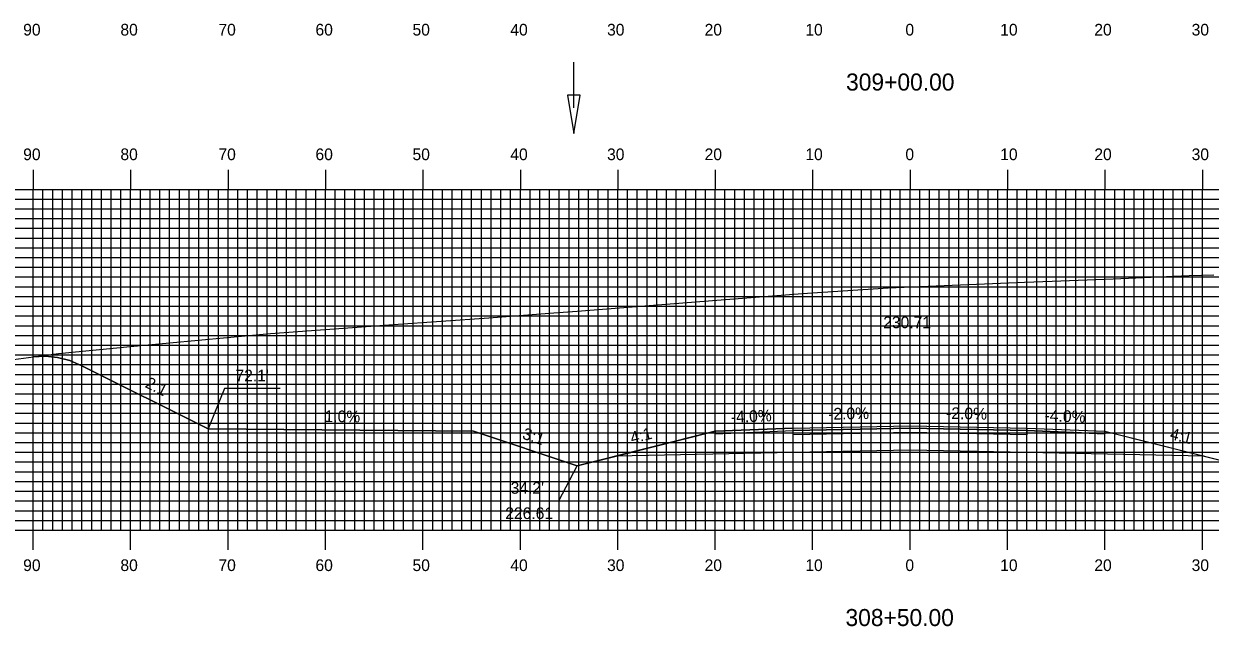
# Model space of a CAD drawing. Extents: x 1817670 to 1818013, y 442591 to 442811.
# Drawn here: x 1817744.6 to 1817866.4, y 442653.8 to 442715.7 of the extents above; entities that cross this region are included whole.
import ezdxf

# ---------------------------------------------------------------- set-up
doc = ezdxf.new("R2010")
doc.units = 0
for name, color, linetype in [('ANNOTATION', 7, 'Continuous'), ('D_Drainage_Ditch_Line', 7, 'Continuous'), ('D_Roadway_Centerline', 7, 'Continuous'), ('D_Roadway_Centerline_Text', 7, 'Continuous'), ('D_Roadway_Edge_Shoulder', 7, 'Continuous'), ('D_Roadway_Edge_TW', 7, 'Continuous'), ('D_Roadway_Pavement', 7, 'Continuous'), ('D_Roadway_SlopeLines', 7, 'Continuous'), ('D_Roadway_SubGrade', 7, 'Continuous'), ('H_V ANNOTATION', 7, 'Continuous'), ('MAJOR', 7, 'Continuous'), ('MINOR', 7, 'Continuous'), ('S_Roadway_Centerline', 7, 'Continuous')]:
    doc.layers.add(name, color=color, linetype=linetype)

msp = doc.modelspace()

# ---------------------------------------------------------------- linework, layer by layer
at = {"layer": 'ANNOTATION'}
for points in [[(1817770.94, 442678.22), (1817765.25, 442678.22), (1817763.55, 442674.09)], [(1817793.87, 442666.68), (1817799.56, 442666.68), (1817801.44, 442670.27)]]:
    msp.add_lwpolyline(points, dxfattribs=at)
at = {"layer": 'D_Drainage_Ditch_Line'}
msp.add_line((1817801.1, 442707.03), (1817801.1, 442711.73), dxfattribs=at)
msp.add_lwpolyline([(1817801.76, 442708.35), (1817800.44, 442708.35), (1817801.1, 442704.41)], close=True, dxfattribs=at)
at = {"layer": 'D_Roadway_Centerline'}
msp.add_lwpolyline([(1817745.61, 442681.47), (1817746.86, 442681.54), (1817748.11, 442681.41), (1817749.36, 442681.08), (1817750.61, 442680.56), (1817763.55, 442674.09), (1817790.81, 442673.82), (1817801.44, 442670.27), (1817805.44, 442671.27), (1817815.61, 442673.82), (1817823.61, 442674.14), (1817835.61, 442674.38), (1817847.61, 442674.14), (1817855.61, 442673.82), (1817865.79, 442671.27), (1817869.79, 442670.27), (1817880.42, 442673.82), (1817887.8, 442673.89), (1817920.61, 442690.3), (1817921.86, 442690.85), (1817923.11, 442691.24), (1817924.36, 442691.47), (1817925.61, 442691.56)], dxfattribs=at)
at = {"layer": 'D_Roadway_Edge_Shoulder'}
for points in [[(1817823.61, 442674.14), (1817815.61, 442673.82), (1817815.61, 442673.57), (1817823.61, 442673.89)], [(1817847.61, 442674.14), (1817855.61, 442673.82), (1817855.61, 442673.57), (1817847.61, 442673.89)]]:
    msp.add_lwpolyline(points, close=True, dxfattribs=at)
at = {"layer": 'D_Roadway_Edge_TW'}
msp.add_lwpolyline([(1817823.61, 442673.89), (1817823.61, 442674.14), (1817835.61, 442674.38), (1817847.61, 442674.14), (1817847.61, 442673.89), (1817835.61, 442674.13)], close=True, dxfattribs=at)
at = {"layer": 'D_Roadway_Pavement'}
msp.add_lwpolyline([(1817823.61, 442673.47), (1817823.61, 442673.89), (1817835.61, 442674.13), (1817847.61, 442673.89), (1817847.61, 442673.47), (1817835.61, 442673.71)], close=True, dxfattribs=at)
at = {"layer": 'D_Roadway_SlopeLines'}
for points in [[(1817790.81, 442673.82), (1817763.55, 442674.09), (1817750.61, 442680.56), (1817749.36, 442681.08), (1817748.11, 442681.41), (1817746.86, 442681.54), (1817745.61, 442681.47)], [(1817801.44, 442670.27), (1817790.81, 442673.82)], [(1817815.61, 442673.82), (1817801.44, 442670.27)], [(1817855.61, 442673.82), (1817869.79, 442670.27)]]:
    msp.add_lwpolyline(points, dxfattribs=at)
at = {"layer": 'D_Roadway_SubGrade'}
msp.add_lwpolyline([(1817823.61, 442671.64), (1817805.44, 442671.27), (1817815.61, 442673.82), (1817815.61, 442673.57), (1817823.61, 442673.89), (1817835.61, 442674.13), (1817847.61, 442673.89), (1817855.61, 442673.57), (1817855.61, 442673.82), (1817865.79, 442671.27), (1817847.61, 442671.64), (1817835.61, 442671.88)], close=True, dxfattribs=at)
at = {"layer": 'MAJOR'}
for p, q in [((1817745.61, 442700.67), (1817745.61, 442698.67)), ((1817755.61, 442700.67), (1817755.61, 442698.67)), ((1817765.61, 442700.67), (1817765.61, 442698.67)), ((1817775.61, 442700.67), (1817775.61, 442698.67)), ((1817785.61, 442700.67), (1817785.61, 442698.67)), ((1817795.61, 442700.67), (1817795.61, 442698.67)), ((1817805.61, 442700.67), (1817805.61, 442698.67)), ((1817815.61, 442700.67), (1817815.61, 442698.67)), ((1817825.61, 442700.67), (1817825.61, 442698.67)), ((1817835.61, 442700.67), (1817835.61, 442698.67)), ((1817845.61, 442700.67), (1817845.61, 442698.67)), ((1817855.61, 442700.67), (1817855.61, 442698.67)), ((1817865.61, 442700.67), (1817865.61, 442698.67)), ((1817695.61, 442698.67), (1817975.61, 442698.67)), ((1817695.61, 442698.67), (1817975.61, 442698.67)), ((1817745.61, 442663.67), (1817745.61, 442698.67)), ((1817755.61, 442663.67), (1817755.61, 442698.67)), ((1817765.61, 442663.67), (1817765.61, 442698.67)), ((1817775.61, 442663.67), (1817775.61, 442698.67)), ((1817785.61, 442663.67), (1817785.61, 442698.67)), ((1817795.61, 442663.67), (1817795.61, 442698.67)), ((1817805.61, 442663.67), (1817805.61, 442698.67)), ((1817815.61, 442663.67), (1817815.61, 442698.67)), ((1817825.61, 442663.67), (1817825.61, 442698.67)), ((1817835.61, 442663.67), (1817835.61, 442698.67)), ((1817845.61, 442663.67), (1817845.61, 442698.67)), ((1817855.61, 442663.67), (1817855.61, 442698.67)), ((1817865.61, 442663.67), (1817865.61, 442698.67)), ((1817695.61, 442693.67), (1817975.61, 442693.67)), ((1817695.61, 442688.67), (1817975.61, 442688.67)), ((1817695.61, 442683.67), (1817975.61, 442683.67)), ((1817695.61, 442678.67), (1817975.61, 442678.67)), ((1817695.61, 442673.67), (1817975.61, 442673.67)), ((1817695.61, 442668.67), (1817975.61, 442668.67)), ((1817695.61, 442663.67), (1817975.61, 442663.67)), ((1817695.61, 442663.67), (1817975.61, 442663.67)), ((1817745.61, 442661.66), (1817745.61, 442663.67)), ((1817755.61, 442661.66), (1817755.61, 442663.67)), ((1817765.61, 442661.66), (1817765.61, 442663.67)), ((1817775.61, 442661.66), (1817775.61, 442663.67)), ((1817785.61, 442661.66), (1817785.61, 442663.67)), ((1817795.61, 442661.66), (1817795.61, 442663.67)), ((1817805.61, 442661.66), (1817805.61, 442663.67)), ((1817815.61, 442661.66), (1817815.61, 442663.67)), ((1817825.61, 442661.66), (1817825.61, 442663.67)), ((1817835.61, 442661.66), (1817835.61, 442663.67)), ((1817845.61, 442661.66), (1817845.61, 442663.67)), ((1817855.61, 442661.66), (1817855.61, 442663.67)), ((1817865.61, 442661.66), (1817865.61, 442663.67))]:
    msp.add_line(p, q, dxfattribs=at)
at = {"layer": 'MINOR'}
for p, q in [((1817746.61, 442663.67), (1817746.61, 442698.67)), ((1817747.61, 442663.67), (1817747.61, 442698.67)), ((1817748.61, 442663.67), (1817748.61, 442698.67)), ((1817749.61, 442663.67), (1817749.61, 442698.67)), ((1817750.61, 442663.67), (1817750.61, 442698.67)), ((1817751.61, 442663.67), (1817751.61, 442698.67)), ((1817752.61, 442663.67), (1817752.61, 442698.67)), ((1817753.61, 442663.67), (1817753.61, 442698.67)), ((1817754.61, 442663.67), (1817754.61, 442698.67)), ((1817756.61, 442663.67), (1817756.61, 442698.67)), ((1817757.61, 442663.67), (1817757.61, 442698.67)), ((1817758.61, 442663.67), (1817758.61, 442698.67)), ((1817759.61, 442663.67), (1817759.61, 442698.67)), ((1817760.61, 442663.67), (1817760.61, 442698.67)), ((1817761.61, 442663.67), (1817761.61, 442698.67)), ((1817762.61, 442663.67), (1817762.61, 442698.67)), ((1817763.61, 442663.67), (1817763.61, 442698.67)), ((1817764.61, 442663.67), (1817764.61, 442698.67)), ((1817766.61, 442663.67), (1817766.61, 442698.67)), ((1817767.61, 442663.67), (1817767.61, 442698.67)), ((1817768.61, 442663.67), (1817768.61, 442698.67)), ((1817769.61, 442663.67), (1817769.61, 442698.67)), ((1817770.61, 442663.67), (1817770.61, 442698.67)), ((1817771.61, 442663.67), (1817771.61, 442698.67)), ((1817772.61, 442663.67), (1817772.61, 442698.67)), ((1817773.61, 442663.67), (1817773.61, 442698.67)), ((1817774.61, 442663.67), (1817774.61, 442698.67)), ((1817776.61, 442663.67), (1817776.61, 442698.67)), ((1817777.61, 442663.67), (1817777.61, 442698.67)), ((1817778.61, 442663.67), (1817778.61, 442698.67)), ((1817779.61, 442663.67), (1817779.61, 442698.67)), ((1817780.61, 442663.67), (1817780.61, 442698.67)), ((1817781.61, 442663.67), (1817781.61, 442698.67)), ((1817782.61, 442663.67), (1817782.61, 442698.67)), ((1817783.61, 442663.67), (1817783.61, 442698.67)), ((1817784.61, 442663.67), (1817784.61, 442698.67)), ((1817786.61, 442663.67), (1817786.61, 442698.67)), ((1817787.61, 442663.67), (1817787.61, 442698.67)), ((1817788.61, 442663.67), (1817788.61, 442698.67)), ((1817789.61, 442663.67), (1817789.61, 442698.67)), ((1817790.61, 442663.67), (1817790.61, 442698.67)), ((1817791.61, 442663.67), (1817791.61, 442698.67)), ((1817792.61, 442663.67), (1817792.61, 442698.67)), ((1817793.61, 442663.67), (1817793.61, 442698.67)), ((1817794.61, 442663.67), (1817794.61, 442698.67)), ((1817796.61, 442663.67), (1817796.61, 442698.67)), ((1817797.61, 442663.67), (1817797.61, 442698.67)), ((1817798.61, 442663.67), (1817798.61, 442698.67)), ((1817799.61, 442663.67), (1817799.61, 442698.67)), ((1817800.61, 442663.67), (1817800.61, 442698.67)), ((1817801.61, 442663.67), (1817801.61, 442698.67)), ((1817802.61, 442663.67), (1817802.61, 442698.67)), ((1817803.61, 442663.67), (1817803.61, 442698.67)), ((1817804.61, 442663.67), (1817804.61, 442698.67)), ((1817806.61, 442663.67), (1817806.61, 442698.67)), ((1817807.61, 442663.67), (1817807.61, 442698.67)), ((1817808.61, 442663.67), (1817808.61, 442698.67)), ((1817809.61, 442663.67), (1817809.61, 442698.67)), ((1817810.61, 442663.67), (1817810.61, 442698.67)), ((1817811.61, 442663.67), (1817811.61, 442698.67)), ((1817812.61, 442663.67), (1817812.61, 442698.67)), ((1817813.61, 442663.67), (1817813.61, 442698.67)), ((1817814.61, 442663.67), (1817814.61, 442698.67)), ((1817816.61, 442663.67), (1817816.61, 442698.67)), ((1817817.61, 442663.67), (1817817.61, 442698.67)), ((1817818.61, 442663.67), (1817818.61, 442698.67)), ((1817819.61, 442663.67), (1817819.61, 442698.67)), ((1817820.61, 442663.67), (1817820.61, 442698.67)), ((1817821.61, 442663.67), (1817821.61, 442698.67)), ((1817822.61, 442663.67), (1817822.61, 442698.67)), ((1817823.61, 442663.67), (1817823.61, 442698.67)), ((1817824.61, 442663.67), (1817824.61, 442698.67)), ((1817826.61, 442663.67), (1817826.61, 442698.67)), ((1817827.61, 442663.67), (1817827.61, 442698.67)), ((1817828.61, 442663.67), (1817828.61, 442698.67)), ((1817829.61, 442663.67), (1817829.61, 442698.67)), ((1817830.61, 442663.67), (1817830.61, 442698.67)), ((1817831.61, 442663.67), (1817831.61, 442698.67)), ((1817832.61, 442663.67), (1817832.61, 442698.67)), ((1817833.61, 442663.67), (1817833.61, 442698.67)), ((1817834.61, 442663.67), (1817834.61, 442698.67)), ((1817836.61, 442663.67), (1817836.61, 442698.67)), ((1817837.61, 442663.67), (1817837.61, 442698.67)), ((1817838.61, 442663.67), (1817838.61, 442698.67)), ((1817839.61, 442663.67), (1817839.61, 442698.67)), ((1817840.61, 442663.67), (1817840.61, 442698.67)), ((1817841.61, 442663.67), (1817841.61, 442698.67)), ((1817842.61, 442663.67), (1817842.61, 442698.67)), ((1817843.61, 442663.67), (1817843.61, 442698.67)), ((1817844.61, 442663.67), (1817844.61, 442698.67)), ((1817846.61, 442663.67), (1817846.61, 442698.67)), ((1817847.61, 442663.67), (1817847.61, 442698.67)), ((1817848.61, 442663.67), (1817848.61, 442698.67)), ((1817849.61, 442663.67), (1817849.61, 442698.67)), ((1817850.61, 442663.67), (1817850.61, 442698.67)), ((1817851.61, 442663.67), (1817851.61, 442698.67)), ((1817852.61, 442663.67), (1817852.61, 442698.67)), ((1817853.61, 442663.67), (1817853.61, 442698.67)), ((1817854.61, 442663.67), (1817854.61, 442698.67)), ((1817856.61, 442663.67), (1817856.61, 442698.67)), ((1817857.61, 442663.67), (1817857.61, 442698.67)), ((1817858.61, 442663.67), (1817858.61, 442698.67)), ((1817859.61, 442663.67), (1817859.61, 442698.67)), ((1817860.61, 442663.67), (1817860.61, 442698.67)), ((1817861.61, 442663.67), (1817861.61, 442698.67)), ((1817862.61, 442663.67), (1817862.61, 442698.67)), ((1817863.61, 442663.67), (1817863.61, 442698.67)), ((1817864.61, 442663.67), (1817864.61, 442698.67)), ((1817695.61, 442697.67), (1817975.61, 442697.67)), ((1817695.61, 442696.67), (1817975.61, 442696.67)), ((1817695.61, 442695.67), (1817975.61, 442695.67)), ((1817695.61, 442694.67), (1817975.61, 442694.67)), ((1817695.61, 442692.67), (1817975.61, 442692.67)), ((1817695.61, 442691.67), (1817975.61, 442691.67)), ((1817695.61, 442690.67), (1817975.61, 442690.67)), ((1817695.61, 442689.67), (1817975.61, 442689.67)), ((1817695.61, 442687.67), (1817975.61, 442687.67)), ((1817695.61, 442686.67), (1817975.61, 442686.67)), ((1817695.61, 442685.67), (1817975.61, 442685.67)), ((1817695.61, 442684.67), (1817975.61, 442684.67)), ((1817695.61, 442682.67), (1817975.61, 442682.67)), ((1817695.61, 442681.67), (1817975.61, 442681.67)), ((1817695.61, 442680.67), (1817975.61, 442680.67)), ((1817695.61, 442679.67), (1817975.61, 442679.67)), ((1817695.61, 442677.67), (1817975.61, 442677.67)), ((1817695.61, 442676.67), (1817975.61, 442676.67)), ((1817695.61, 442675.67), (1817975.61, 442675.67)), ((1817695.61, 442674.67), (1817975.61, 442674.67)), ((1817695.61, 442672.67), (1817975.61, 442672.67)), ((1817695.61, 442671.67), (1817975.61, 442671.67)), ((1817695.61, 442670.67), (1817975.61, 442670.67)), ((1817695.61, 442669.67), (1817975.61, 442669.67)), ((1817695.61, 442667.67), (1817975.61, 442667.67)), ((1817695.61, 442666.67), (1817975.61, 442666.67)), ((1817695.61, 442665.67), (1817975.61, 442665.67)), ((1817695.61, 442664.67), (1817975.61, 442664.67))]:
    msp.add_line(p, q, dxfattribs=at)
at = {"layer": 'S_Roadway_Centerline'}
msp.add_lwpolyline([(1817695.61, 442675.89), (1817697.5, 442676.08), (1817704.01, 442676.85), (1817715.14, 442677.95), (1817728.79, 442679.32), (1817731.55, 442679.62), (1817732.78, 442679.75), (1817748.2, 442681.82), (1817755.93, 442682.57), (1817764.76, 442683.38), (1817769.96, 442683.88), (1817782.59, 442684.79), (1817792.39, 442685.49), (1817799.05, 442686), (1817801.45, 442686.16), (1817815.76, 442687.29), (1817824.57, 442687.98), (1817833.37, 442688.54), (1817847.37, 442689.15), (1817850.18, 442689.23), (1817856.46, 442689.49), (1817864.27, 442689.84), (1817866.79, 442689.88)], dxfattribs=at)

# ---------------------------------------------------------------- texts
at = {"layer": 'ANNOTATION'}
for s, p in [("72.1'", (1817766.37, 442678.95)), ("34.2'", (1817794.61, 442667.41)), ('226.61', (1817794.06, 442664.81))]:
    msp.add_text(s, height=1.2, dxfattribs=at).set_placement(p)
for s, rotation, p in [('2:1', 333.4349, (1817757.01, 442678.39)), ('1.0%', 359.4271, (1817775.51, 442674.77)), ('-4.0%', 2.2906, (1817817.24, 442674.69)), ('-2.0%', 1.1458, (1817827.22, 442675.01)), ('-2.0%', 358.8542, (1817839.3, 442675.1)), ('-4.0%', 357.7094, (1817849.4, 442674.87)), ('3:1', 341.5651, (1817795.73, 442673.09)), ('4:1', 14.0362, (1817807.06, 442672.54)), ('4:1', 345.9638, (1817862.21, 442673.03))]:
    msp.add_text(s, height=1.2, rotation=rotation, dxfattribs=at).set_placement(p)
at = {"layer": 'D_Roadway_Centerline'}
for s, p in [('C', (1817835.61, 442674.38)), ('L', (1817835.61, 442674.37))]:
    msp.add_text(s, height=0.0146, dxfattribs=at).set_placement(p)
at = {"layer": 'D_Roadway_Centerline_Text'}
msp.add_text('230.71', height=1.2, dxfattribs=at).set_placement((1817832.85, 442684.41))
at = {"layer": 'H_V ANNOTATION'}
for s, height, p in [('90', 1.2, (1817744.58, 442714.47)), ('80', 1.2, (1817754.56, 442714.47)), ('70', 1.2, (1817764.62, 442714.47)), ('60', 1.2, (1817774.58, 442714.47)), ('50', 1.2, (1817784.54, 442714.47)), ('40', 1.2, (1817794.58, 442714.47)), ('30', 1.2, (1817804.51, 442714.47)), ('20', 1.2, (1817814.52, 442714.47)), ('10', 1.2, (1817824.86, 442714.47)), ('0', 1.2, (1817835.13, 442714.47)), ('10', 1.2, (1817844.86, 442714.47)), ('20', 1.2, (1817854.52, 442714.47)), ('30', 1.2, (1817864.51, 442714.47)), ('309+00.00', 1.75, (1817829.04, 442708.82)), ('90', 1.2, (1817744.58, 442701.67)), ('80', 1.2, (1817754.56, 442701.67)), ('70', 1.2, (1817764.62, 442701.67)), ('60', 1.2, (1817774.58, 442701.67)), ('50', 1.2, (1817784.54, 442701.67)), ('40', 1.2, (1817794.58, 442701.67)), ('30', 1.2, (1817804.51, 442701.67)), ('20', 1.2, (1817814.52, 442701.67)), ('10', 1.2, (1817824.86, 442701.67)), ('0', 1.2, (1817835.13, 442701.67)), ('10', 1.2, (1817844.86, 442701.67)), ('20', 1.2, (1817854.52, 442701.67)), ('30', 1.2, (1817864.51, 442701.67)), ('90', 1.2, (1817744.58, 442659.47)), ('80', 1.2, (1817754.56, 442659.47)), ('70', 1.2, (1817764.62, 442659.47)), ('60', 1.2, (1817774.58, 442659.47)), ('50', 1.2, (1817784.54, 442659.47)), ('40', 1.2, (1817794.58, 442659.47)), ('30', 1.2, (1817804.51, 442659.47)), ('20', 1.2, (1817814.52, 442659.47)), ('10', 1.2, (1817824.86, 442659.47)), ('0', 1.2, (1817835.13, 442659.47)), ('10', 1.2, (1817844.86, 442659.47)), ('20', 1.2, (1817854.52, 442659.47)), ('30', 1.2, (1817864.51, 442659.47)), ('308+50.00', 1.75, (1817828.98, 442653.82))]:
    msp.add_text(s, height=height, dxfattribs=at).set_placement(p)

doc.saveas('drawing.dxf')
